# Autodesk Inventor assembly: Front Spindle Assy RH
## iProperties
Length Units: 11269
Angle Units: 11279
Time Units: 11290
Mass Units: 11283
Shininess: 3
Angle Display Precision: 2
Document Length Units: 11269
Document Angle Units: 11279
Document Time Units: 11290
Document Mass Units: 11283
Document Length Units Precision: 3
Document Angle Units Precision: 2
Compacted: True
Created: 2001-08
Part Number: Front Spindle Assy RH
Document SubType Name: Assembly
Designer: Martin Budgell
Density: 0.0
Volumn: 0.0
Area: 0.0
PropertySet Name: Model Information
Control State: 0
Master: False
Checked Out: False
Author: Martin Budgell
